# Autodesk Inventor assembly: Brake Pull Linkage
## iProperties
Shininess: 64.0
Angle Display Precision: 2
Document Length Units: 11269
Document Angle Units: 11279
Document Time Units: 11290
Document Mass Units: 11283
Document Length Units Precision: 3
Document Angle Units Precision: 2
Compacted: True
Created: 2001-09
Part Number: Brake Pull Linkage
Document SubType Name: Assembly
Designer: Martin Budgell
Density: 0.0
Volumn: 0.0
Area: 0.0
PropertySet Name: Model Information
Control State: 0
Master: False
Checked Out: False
Author: Martin Budgell
